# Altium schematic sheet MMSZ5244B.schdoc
size 127 x 101 mm
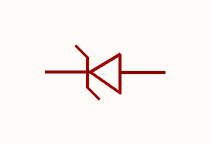
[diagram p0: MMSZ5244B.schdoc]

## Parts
ZD?  mmsz5244b  [SOD-123_L2.8-W1.8-LS3.7-RD]  (value not drawn)

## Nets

Not connected (* = marked no-connect by the designer): ZD? 1(K) 2(A)

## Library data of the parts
ZD? = mmsz5244b: 二极管配置:1个独立式;稳压值(标称值):14V;稳压值(范围值):13.3V~14.7V;耗散功率(Pd):350mW;; Manufacturer: CJ(江苏长电/长晶); AddInBom: yes; ModelId: 7884390a25fb4c08947731ebfba7e3f8; ModelTransform: 144.8816,62.992,0,0,0,0,0,0,0; Diode Configuration: 1个独立式; Zener Voltage(Nom): 14V; Reverse Leakage Current (Ir): 100nA; Pd - Power Dissipation: 350mW; Impedance(Zzt): 15Ω; Impedance(Zzk): 600Ω; Operating Junction Temperature Range: -55℃~+150℃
